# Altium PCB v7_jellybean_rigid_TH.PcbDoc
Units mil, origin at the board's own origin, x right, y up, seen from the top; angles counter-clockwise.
Board outline 581.17 x 314.34 mil, 2 copper layers (Top Layer, Bottom Layer), stack 26.422 mil thick; 26 components, 15 nets, 63 pads, 13 vias.
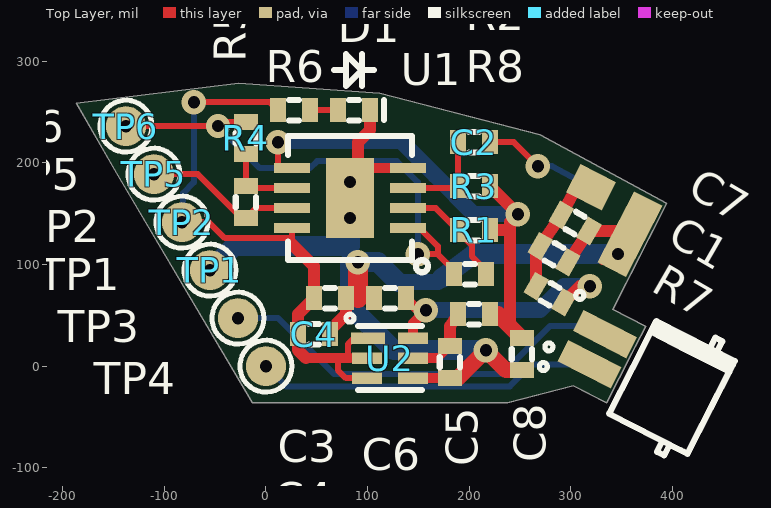
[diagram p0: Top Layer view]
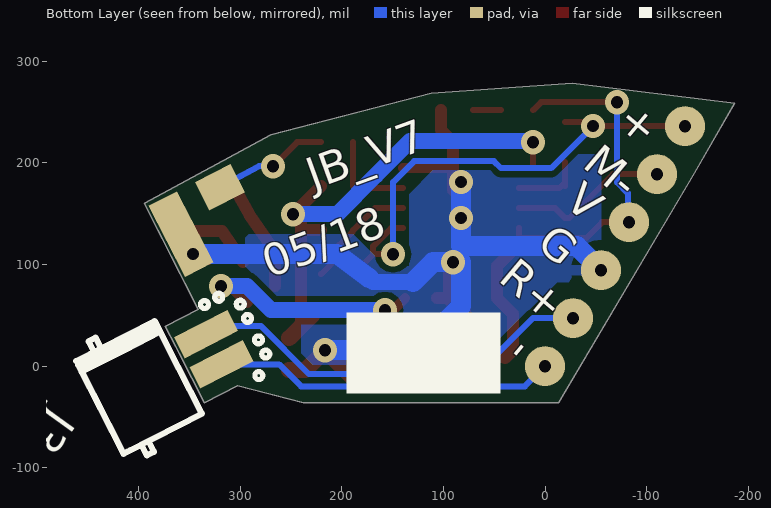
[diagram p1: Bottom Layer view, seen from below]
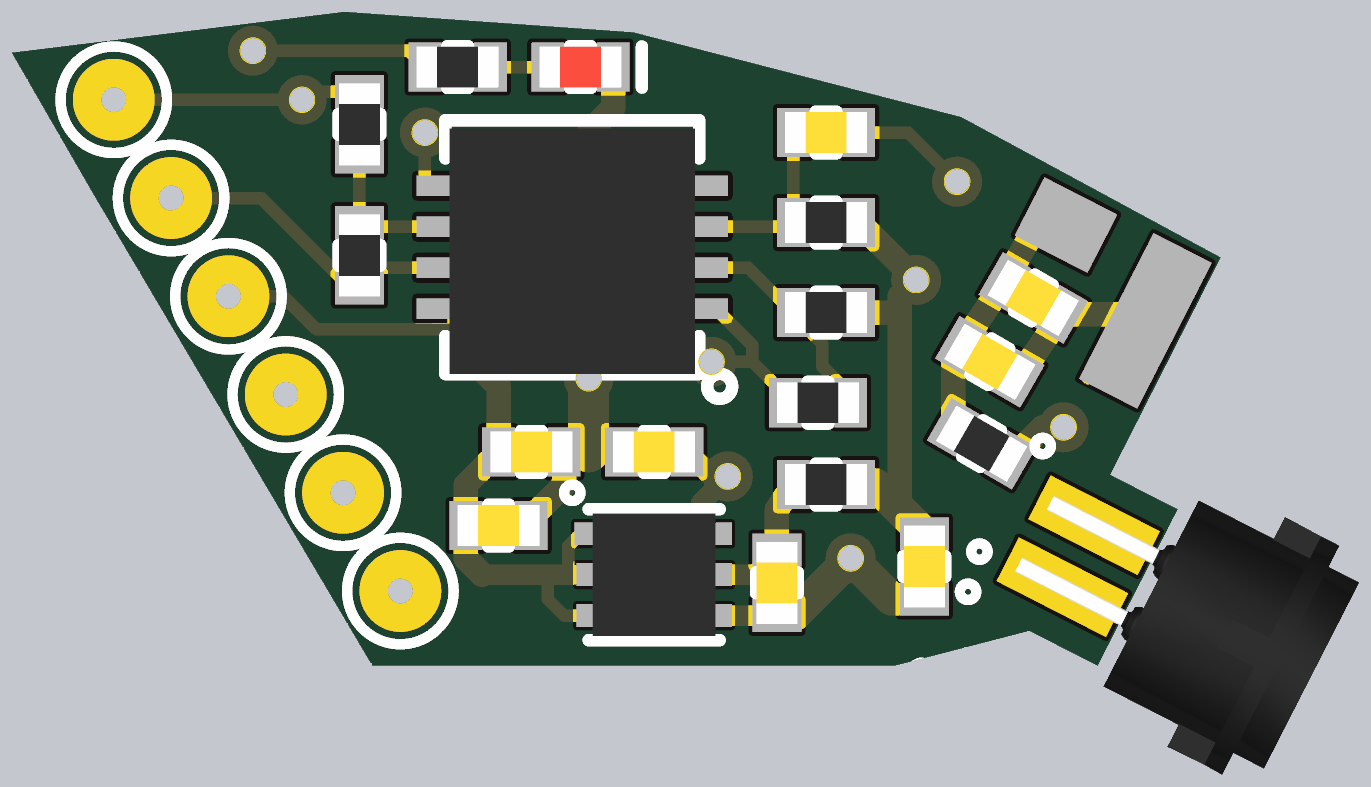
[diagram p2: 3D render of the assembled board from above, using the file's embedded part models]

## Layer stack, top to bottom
Top Solder: solder mask 0.4, Solder Resist, Dk 3.5
Top Layer: signal copper 1.4
Dielectric 1: dielectric 23.622, FR-4, Dk 4.8
Bottom Layer: signal copper 1.4
Bottom Solder: solder mask 0.4, Solder Resist, Dk 3.5

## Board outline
302.45,-19.11 237.78,-35.87 -9.46,-35.87 -13.47,-35.87 -147.16,190.21 -186.77,258.82 -26.83,278.47 111.98,268.61 269.63,227.86 394.39,160.36 341.23,55.87 373.7,39.25 363.62,19.55 360.03,12.53 335.26,-35.87

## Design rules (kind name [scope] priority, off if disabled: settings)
Clearance [All] p1: gap=6 ignorepadtopadclearanceinfootprint=FALSE except(0: Arc-Hole Track-Hole SMDPad-Hole THPad-Hole Via-Hole Fill-Hole Poly-Hole Region-Hole Text-Hole)
MinimumSolderMaskSliver [All] p1: minsoldermaskwidth=5
PolygonConnect [All] p1: thpad.connectstyle=Relief thpad.reliefconductorwidth=10 thpad.reliefentries=4 thpad.polygonreliefangle="90 Angle" thpad.airgapwidth=10 smdpad.connectstyle=Relief smdpad.reliefconductorwidth=10 smdpad.reliefentries=4 smdpad.polygonreliefangle="90 Angle" smdpad.airgapwidth=10 via.connectstyle=Direct via.reliefconductorwidth=10 via.reliefentries=4 via.polygonreliefangle="90 Angle" via.airgapwidth=10
RoutingVias [All] p1: holewidth=12.01 width=24.02 viastyle="Through Hole" minholewidth=12.01 minwidth=24.02 maxholewidth=28 maxwidth=50
SolderMaskExpansion [All] p1: expansion=4
Width [All] p1: maxlimit=19.68 minlimit=6 preferedwidth=6
29 further rules are at their usual default settings.

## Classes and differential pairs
net class PWR: 1V2 2V5 GND VIN

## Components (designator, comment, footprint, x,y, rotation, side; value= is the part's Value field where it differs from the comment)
C1 "100nF" C0402MIN 283.45,110.22 r330 top
C2 "10uF" C0402MIN 204.71,220.46 r180 top
C3 "100nF" C0402MIN 62.98,66.91 r180 top
C4 "1uF" C0402MIN 47.23,31.48 r0 top
C5 "1uF" C0402MIN 181.09,3.92 r270 top
C6 "1uF" C0402MIN 122.03,66.91 r180 top
C7 "10uF" C0402MIN 304.32,140.93 r150 top
C8 "10uF" C0402MIN 251.96,11.8 r270 top
D1 "LED, Green" LED0402MIN 86.6,251.95 r0 top
J3 "CS44_Sonion" "CS44_SOCKET_TH - EDGE - SONION" 361.01,-1.2 r242.9 bottom
R1 "Resistor" R0402MIN 204.71,133.84 r0 top value=100
R2 "Resistor" R0402MIN 200.77,90.54 r180 top value=10K
R3 "Resistor" R0402MIN 204.71,177.15 r0 top value=10K
R4 "Resistor" R0402MIN -19.7,224.39 r270 top value=1K0
R5 "Resistor" R0402MIN -19.7,161.4 r270 top value=1K0
R6 "Resistor" R0402MIN 27.55,251.95 r180 top value=1K0
R7 "Resistor" R0402MIN 279.51,70.85 r150 top value=1K0
R8 "Resistor" R0402MIN 204.71,51.17 r0 top value=1K0
TP1 "Not A Part" TP_32AWG -55.12,94.49 r90 top
TP2 "Not A Part" TP_32AWG -82.68,141.73 r90 top
TP3 "Not A Part" TP_32AWG -27.56,47.24 r90 top
TP4 "Not A Part" TP_32AWG 0,0 r90 top
TP5 "Not A Part" TP_32AWG -110.24,188.98 r90 top
TP6 "Not A Part" TP_32AWG -137.8,236.22 r90 top
U1 "OPA1612 SON-8" SON-8 82.66,165.34 r90 top
U2 "TLV7111225" TLV711X 122.03,7.86 r270 top

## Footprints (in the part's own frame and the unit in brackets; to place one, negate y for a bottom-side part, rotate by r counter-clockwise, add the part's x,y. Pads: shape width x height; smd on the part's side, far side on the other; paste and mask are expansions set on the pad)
C0402MIN [mm] "absolute minimum footprint for 0402 caps"
  rect 0.4x0.6 smd mask+0.05: 1(-0.4,0) 2(0.4,0)
  silkscreen extent -0.13,-0.25 0.13,0.25, body extent -0.5,-0.25 0.5,0.25, height 0.55
"CS44_SOCKET_TH - EDGE - SONION" [mm] "Edge mounted CS44. Requires 0.6mm PCB thickness. For SONION cables"
  rect 0.6x1.5 smd far side paste-1 mask+0.05: 1(-0.425,1) 2(0.425,1)
  rect 0.6x1.5 smd paste-1 mask+0.05: 3(0.425,1) 4(-0.425,1)
  silkscreen extent -1.6,-2.2 1.6,2.2, body extent -1.57,-2.2 1.57,1.6, height 1.35
LED0402MIN [mm] "absolute minimum footprint for 0402 resistors and caps"
  rect 0.4x0.6 smd mask+0.05: 1(0.4,0) 2(-0.4,0)
  silkscreen extent -0.13,-0.25 0.75,0.25, body extent -0.5,-0.25 0.5,0.25, height 0.35
R0402MIN [mm] "absolute minimum footprint for 0402 resistors"
  rect 0.4x0.6 smd mask+0.05: 1(-0.4,0) 2(0.4,0)
  silkscreen extent -0.13,-0.25 0.13,0.25, body extent -0.5,-0.25 0.5,0.25, height 0.35
SON-8 [mm] "for OPA1612"
  rect 0.25x0.9 smd mask+0.06: 1(-0.75,-1.45) 2(-0.25,-1.45) 3(0.25,-1.45) 4(0.75,-1.45) 5(0.75,1.45) 6(0.25,1.45) 7(-0.25,1.45) 8(-0.75,1.45)
  rect 2x1.2 smd: PAD(0,0)
  silkscreen extent -1.85,-1.95 1.55,1.55, body extent -1.55,-1.5 1.45,1.5, height 0.75
TLV711X [mm]
  rect 0.28x0.85 smd mask+0.04: 1(-0.5,-0.55)
  rect 0.28x0.75 smd mask+0.04: 2(0,-0.575) 3(0.5,-0.575) 4(0.5,0.575) 5(0,0.575) 6(-0.5,0.575)
  silkscreen extent -1.1,-1.1 0.8,0.8, body extent -0.75,-0.75 0.75,0.75, height 0.75
TP_32AWG [mm] "hole+pad for 32AWG wire"
  round 1 hole 0.305 mask+0: 1(0,0)
  silkscreen extent -0.65,-0.65 0.65,0.65

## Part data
C1 C2 C3 C4 C5 C6 C7 C8: library part CAP, "Nonpolarized capacitor", DigikeyPartNumber=Lookup, Package=C0402min, VoltageRating=10V
D1: library part LED, "LED", Color=Green, DigikeyPartNumber=Lookup, Package=LED0402min
J3: "4-pin connector. Specify TH vs. SMD", Manufacturer=Knowles, MfgPartNumber=CS44
R1 R2 R3 R4 R5 R6 R7 R8: library part RES, DigikeyPartNumber=Lookup, Tolerance=1%
TP1 TP2 TP3 TP4 TP5 TP6: library part TP_32AWG, "0.305mm (12mil) hole for 32AWG wire. No BOM item."
U1: library part OPA1612_SON-8, "dual op-amp in SON-8 package", DigikeyPartNumber=296-38367-1-ND, Manufacturer=TI, MfgPartNumber=OPA1612AIDRGR
U2: "TLV7113025, dual linear reg, 1V2+ 2V5", DigikeyPartNumber=296-35049-1-ND, Manufacturer=TI, MfgPartNumber=TLV7111225DSER

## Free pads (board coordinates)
  rect 31.5x39.37 smd rot 62.9 mask+1.97: 1(320.07,175.97)
  rect 31.5x78.74 smd rot 152.9 mask+1.97: 1(358.26,129.91)
  rect 31.5x78.74 smd far side rot 152.9 mask+1.97: 1(358.26,129.91)
  rect 31.5x39.37 smd far side rot 62.9 mask+1.97: 3(320.07,175.97)

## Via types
v1: diameter 24.02, hole 12.01, Top Layer to Bottom Layer, tented both sides, 9 vias
v2: diameter 23.66, hole 11.85, Top Layer to Bottom Layer, tented both sides, 4 vias

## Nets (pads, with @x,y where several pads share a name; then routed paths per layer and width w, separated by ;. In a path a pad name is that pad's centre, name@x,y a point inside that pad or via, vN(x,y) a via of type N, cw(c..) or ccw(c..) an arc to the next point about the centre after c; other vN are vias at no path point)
1V2: C1.1 C7.2 pad.1@320.07,175.97 R7.2 | length 119.7
  Top Layer w11.81: R7.2 265.88,114.16 C1.1 C7.2 pad.1@311.02,185.04
2V5: C8.1 R1.2 R3.2 R8.2 U1.5 | length 514.4
  Top Layer w6: v1(11.78,220.45) 11.78,196.88 13.79,194.87 U1.5 ; R8.2@224.4,51.17 228.33,51.17
  Top Layer w11.81: R1.2 240.14,133.84 ; R3.2 v1(248.02,149.59) 240.14,141.72 240.14,133.84 ; 240.14,39.36 240.14,133.84
  Top Layer w15.75: 228.33,51.17 240.14,39.36 C8.1
  Bottom Layer w15.75: v1(11.78,220.45) 12.91,221.58 132.96,221.58 166.47,188.08 166.47,187.84 204.71,149.59 v1(248.02,149.59)
GND: C1.2 C3.1 C4.2 C5.2 C6.2 C7.1 C8.2 D1.1 pad.1@358.26,129.91 TP1.1 U1.4 U1.PAD U2.4 | length 1157.6
  Top Layer w6: C5.2 C5.2@188.96,-11.83 ; pad.1@330.7,102.35 358.26,129.91 pad.1@355.11,133.06
  Top Layer w9.84: U1.PAD@90.54,194.87 U1.4 ; U2.4 C5.2
  Top Layer w11.81: C4.2@62.98,35.42 78.73,51.17 C3.1 90.55,66.91 C6.2 ; U1.PAD@90.54,173.21 90.54,194.87 90.54,220.46 102.35,232.27 D1.1 ; C1.2 C7.1 pad.1@355.11,133.06
  Top Layer w15.75: C5.2@188.96,-11.83 v1(216.52,15.73) 236.21,-3.95 C8.2
  Top Layer w19.68: 90.54,66.93 v1(90.54,102.35)
  Bottom Layer w15.75: 129.89,82.66 169.28,82.66 173.22,86.6
  Bottom Layer w19.68: TP1.1 -31.51,118.1 82.66,118.1 v2(82.66,145.65) v2(82.66,181.09) ; 129.89,82.66 110.21,102.35 v1(90.54,102.35) 82.66,102.35 82.66,59.04 125.97,15.73 v1(216.52,15.73) ; 173.22,86.6 204.71,110.22 pad.1@338.57,110.22
  other v2: 346.44,110.22
MIC_N: R5.2 TP5.1 U1.7 | length 157.8
  Top Layer w6: TP5.1 -66.93,188.98 -23.61,145.65 R5.2 -9.86,155.5 U1.7
MIC_P: R2.2 R4.1 TP6.1 U1.1 | length 516.2
  Top Layer w6: TP6.1@-137.78,236.21 v2(-47.26,236.21) -43.32,240.14 R4.1 ; U1.1 151.56,135.81 169.28,118.1 169.28,110.22 ; v1@141.72,110.22 v1(149.59,110.22) 169.28,110.22 ; R2.2@188.96,90.54 169.28,110.22
  Bottom Layer w6: v2(-47.26,236.21) -5.93,194.88 43.31,194.88 50.34,201.92 128.76,201.92 149.59,181.09 v1(149.59,110.22)
MIC_RAW: C2.1 pad.3 | length 114.7
  Top Layer w6: C2.1 244.08,220.46 v1(267.7,196.84)
  Bottom Layer w6: v1(267.7,196.84) 281.5,196.84 pad.3
NetC2_2: C2.2 R3.1 U1.3 | length 93.3
  Top Layer w6: U1.3 187,175.18 R3.1 C2.2
NetC5_1: C5.1 R8.1 U2.5 | length 75.2
  Top Layer w7.87: 169.28,7.86 C5.1
  Top Layer w9.84: U2.5 169.28,7.86
  Top Layer w11.81: C5.1 181.09,39.36 R8.1
NetC6_1: C6.1 R7.1 U2.6 | length 260.9
  Top Layer w9.84: C6.1 149.6,55.1 v1(157.45,55.1) 144.67,42.32 U2.6
  Top Layer w11.81: R7.1 308.9,78.73 v1(318.89,78.73)
  Bottom Layer w15.75: v1(157.45,55.1) 269.66,55.1 293.29,78.73 v1(318.89,78.73)
NetD1_2: D1.2 R6.1 | length 27.6
  Top Layer w6: R6.1 D1.2
NetR1_1: R1.1 R2.1 U1.2 | length 114.5
  Top Layer w6: U1.2 167.31,155.5 R1.1 188.96,132.93 202.76,119.13 202.76,108.24 R2.1@220.46,90.54
NetR4_2: R4.2 R5.1 U1.6 | length 71.3
  Top Layer w6: R5.1 R5.1@-19.7,181.09 ; -19.7,200.77 R5.1@-19.7,181.09 ; U1.6 -13.79,175.18 R5.1@-19.7,181.09
REC_N: J3.3 TP4.1 | length 335.6
  Bottom Layer w6: TP4.1 19.87,-19.87 239.97,-19.87 261.69,1.84 J3.3
REC_P: J3.4 TP3.1 | length 406.7
  Bottom Layer w6: TP3.1 11.99,47.24 67.1,-7.87 232.29,-7.87 279.51,39.36 311.01,39.36 318.73,31.63 J3.4
VIN: C3.2 C4.1 R6.2 TP2.1 U1.8 U2.1 U2.2 U2.3 | length 598
  Top Layer w6: TP2.1 -56.16,141.73 -40.39,125.97 25.58,125.97 ; v1(-70.9,259.82) 3.92,259.83 R6.2 ; 25.58,120.06 25.58,125.97 ; U1.8 25.58,125.97 ; 70.87,7.86 70.87,-3.94 78.75,-11.83 U2.3 ; 82.68,7.86 80.65,9.89 80.65,21.59 86.6,27.54 U2.1
  Top Layer w9.84: 39.36,7.86 70.87,7.86 82.68,7.86
  Top Layer w11.81: 25.58,120.06 47.23,98.41 C3.2 31.48,51.17 C4.1 ; C4.1@31.48,35.42 31.48,15.73 39.36,7.86
  Bottom Layer w6: TP2.1 -81.55,142.86 -81.55,170.42 -70.9,181.07 v1(-70.9,259.82)
pads on no net: J3.1 J3.2

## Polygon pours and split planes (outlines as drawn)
GND on Bottom Layer "GND_L02_P000" (solid, pour order 0): -55.12,208.66 94.49,208.66 133.86,169.29 133.86,98.43 157.48,98.43 188.98,129.92 295.28,129.92 295.28,98.43 240.16,43.31 240.16,11.81 228.35,0 70.87,0 -11.81,82.68 -55.12,82.68

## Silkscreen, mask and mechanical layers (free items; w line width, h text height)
Top Overlay:
  lines w6: 66.92,291.32 78.73,291.32 ; 94.48,275.58 94.48,307.07 ; 106.29,291.32 94.48,291.32 ; 78.73,291.32 78.73,307.07 94.48,291.32 ; 78.73,291.32 78.73,275.58 94.48,291.32
Bottom Overlay:
  rectangle: 43.69,-26.79 195.26,52.74
  text "+" at -92.52,259.84 h31.5 r130
  text "M-" at -35.43,196.85 h31.5 r40
  text "JB_V7" at 228.35,173.23 h31.5 r340
  text "V" at -17.72,159.45 h31.5 r40
  text "G" at 9.84,118.11 h31.5 r40
  text "05/18" at 271.65,86.61 h31.5 r340
  text "R+" at 47.24,84.65 h31.5 r40
  text "-" at 21.65,1.97 h31.5 r310
Mechanical 1:
  lines w0.5: -107.65,109.44 -57.46,22.49 ; -101.25,224.33 -97.95,218.62 ; -84.61,195.51 -80.67,188.69 ; -84.55,195.41 -81.25,189.69 ; -38.24,115.19 -34.96,109.52 ; -21.62,86.41 -17.68,79.59 ; -21.59,86.36 -18.26,80.59 ; 297.75,15.57 294.22,8.67 297.81,15.69 ; 309.5,38.52 312.51,44.4 ; 309.45,38.42 313.03,45.43 ; 309.45,38.42 313.03,45.43 ; 309.45,38.42 313.03,45.43 ; -187.2,259.03 -147.39,190.08 -29.12,-14.77 302.39,-19.34 335.38,-36.22 360.48,12.84 374.06,39.37 341.34,56.11 394.75,160.47 269.73,228.11 112.03,268.87 -26.84,278.74 -187.2,259.03 ; -101.31,224.44 -97.38,217.62 -101.31,224.44 ; -38.32,115.34 -34.39,108.52 -38.32,115.34 ; 360.26,12.41 363.85,19.42 360.26,12.41
Mechanical 2:
  the board outline again, w0.51
Mechanical 3:
  lines w6: 66.92,291.32 78.73,291.32 ; 94.48,275.58 94.48,307.07 ; 106.29,291.32 94.48,291.32 ; 78.73,291.32 78.73,307.07 94.48,291.32 ; 78.73,291.32 78.73,275.58 94.48,291.32
  text "R6" at 18.1,247.23 h9.84
  text "D1" at 79.91,247.23 h9.84
  text "R4" at -14.97,218.1 h9.84 r90
  text "C2" at 196.44,215.73 h9.84
  text "R3" at 194.87,172.43 h9.84
  text "U1" at 77.94,160.22 h9.84
  text "R5" at -14.97,154.32 h9.84 r90
  text "C7" at 294.08,140.93 h9.84 r330
  text "R1" at 196.84,128.73 h9.84
  text "C1" at 274,110.61 h9.84 r330
  text "R2" at 192.11,85.81 h9.84
  text "R7" at 270.07,70.85 h9.84 r330
  text "C3" at 55.5,62.19 h9.84
  text "C6" at 113.37,61.8 h9.84
  text "R8" at 197.23,46.05 h9.84
  text "C4" at 37.39,26.36 h9.84
  text "C8" at 257.07,6.28 h9.84 r90
  text "U2" at 114.16,2.74 h9.84
  text "C5" at 185.42,-2.38 h9.84 r90
  text "J3" at 394.08,-30.33 h9.84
